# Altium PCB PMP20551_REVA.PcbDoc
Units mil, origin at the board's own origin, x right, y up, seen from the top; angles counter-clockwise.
Board outline 3500 x 1900 mil, 2 copper layers (Top Layer, Bottom Layer), stack 62 mil thick; 71 components, 27 nets, 155 pads, 31 vias.
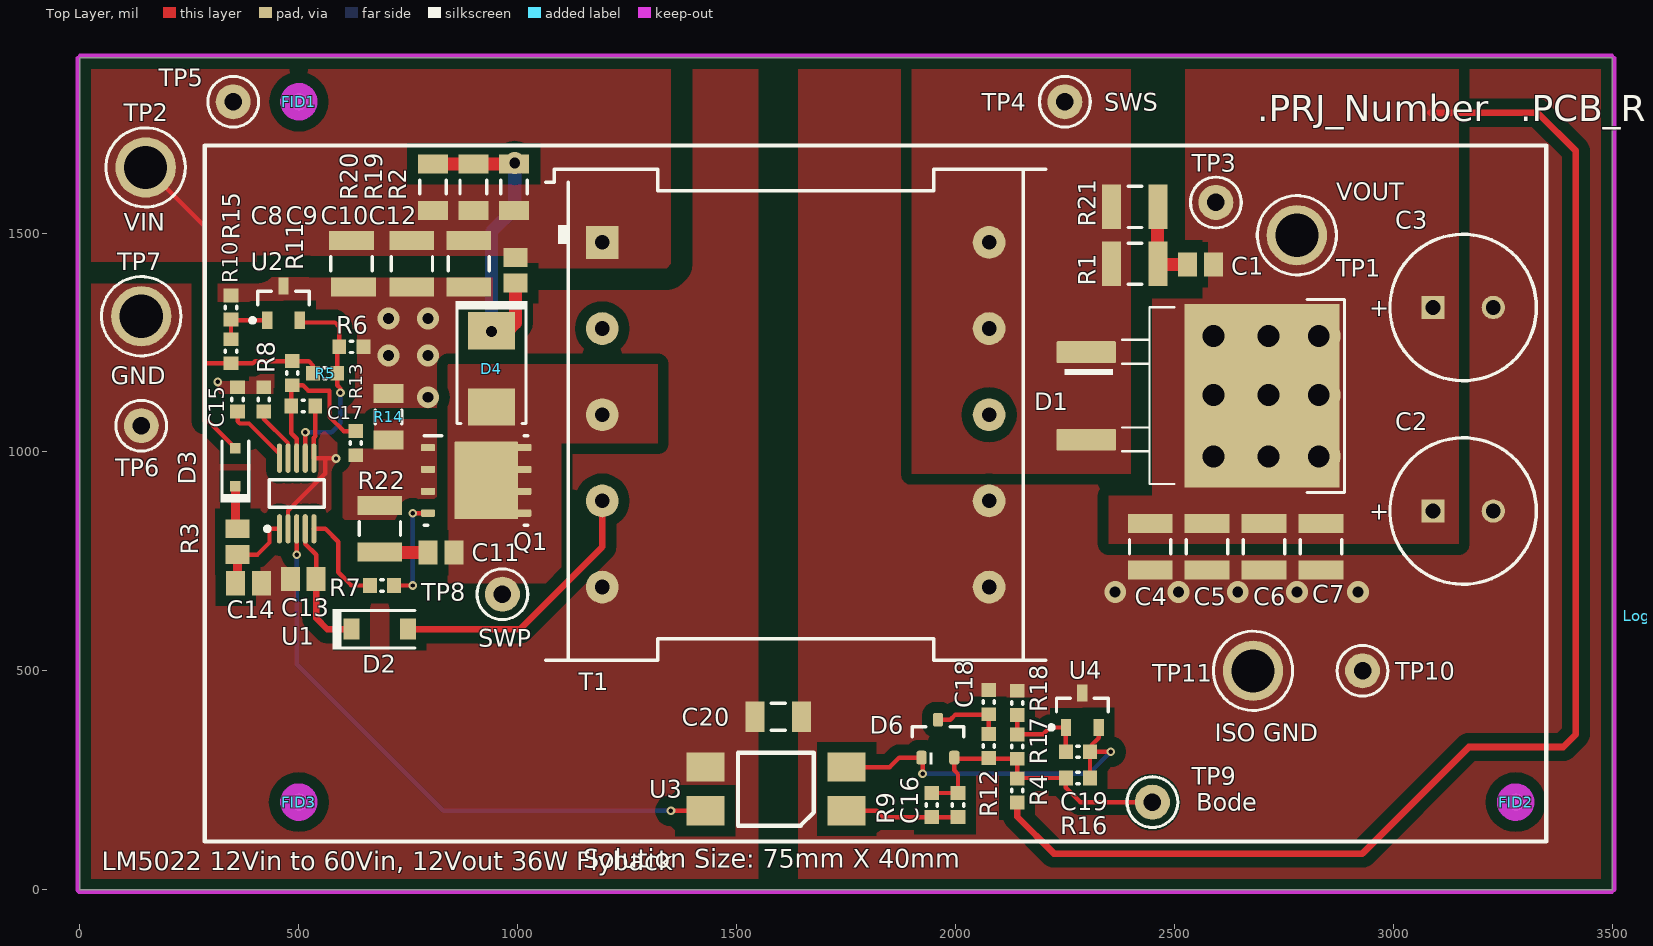
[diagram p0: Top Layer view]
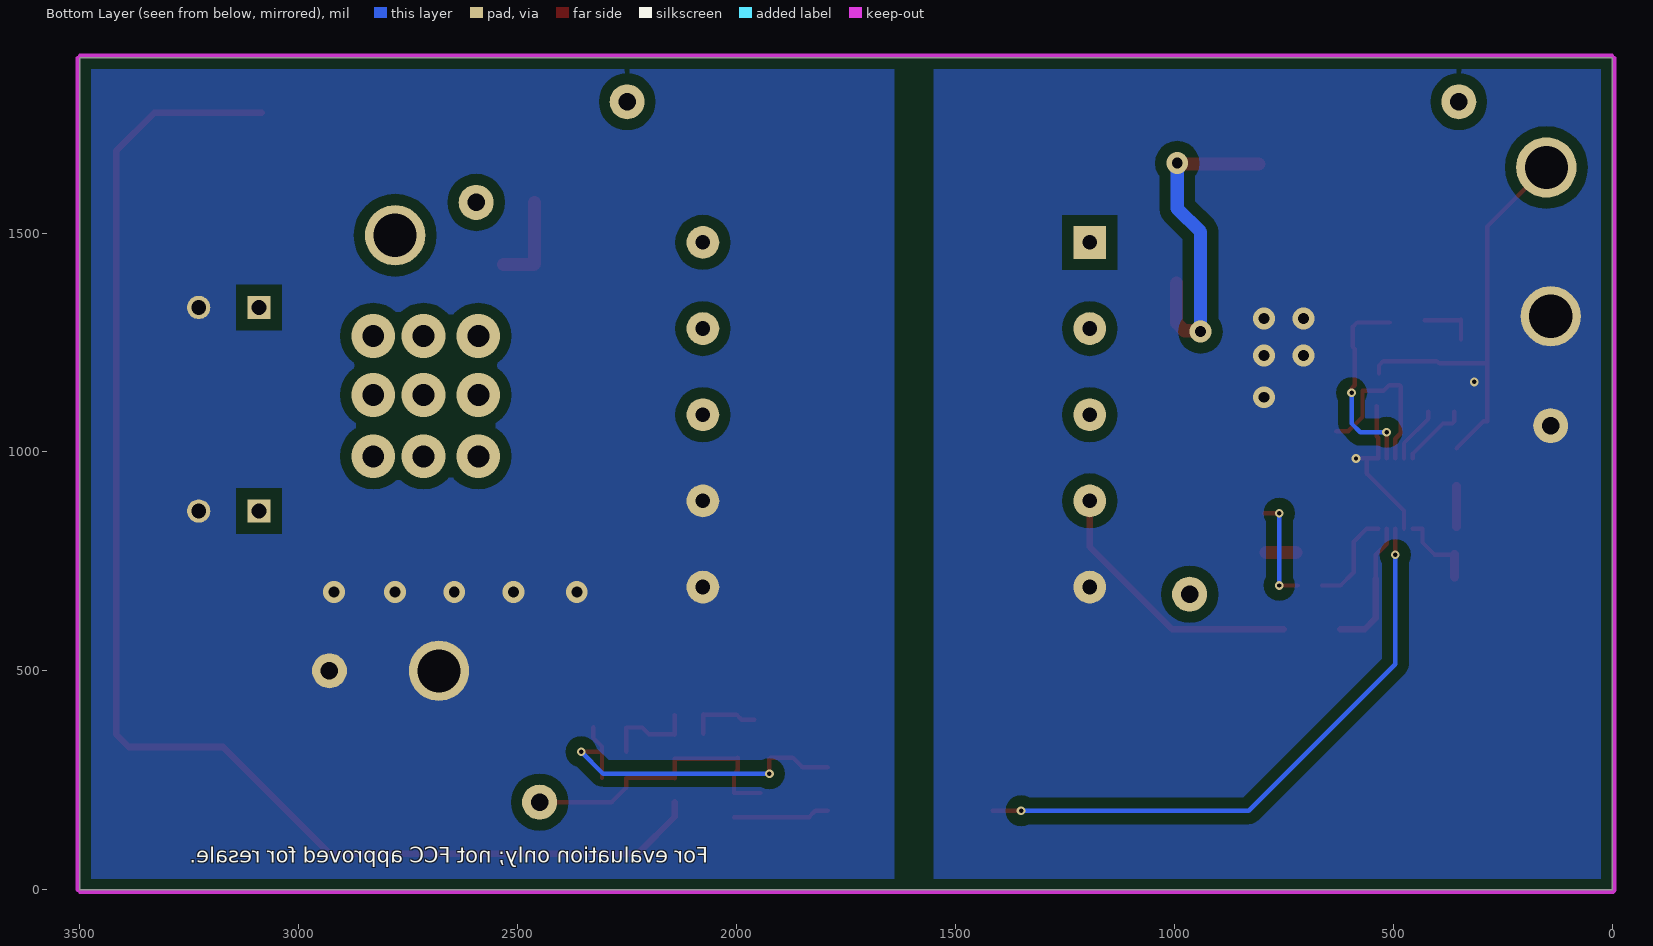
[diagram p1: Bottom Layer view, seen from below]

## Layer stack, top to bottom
Top Solder: solder mask 0.4, Solder Resist, Dk 3.5
Top Layer: signal copper 1.4
Dielectric1: core 59.2, FR-4, Dk 4.8
Bottom Layer: signal copper 1.4
Bottom Solder: solder mask 0.4, Solder Resist, Dk 3.5

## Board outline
0,0 3500,0 3500,1900 0,1900

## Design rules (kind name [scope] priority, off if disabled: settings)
AcuteAngle [All] p1: minimum=4.50000000000000E+0001 checktracksonly=FALSE
AssemblyTestPointUsage [All] p1: valid=2
Clearance Clearance_GND [(InPolygon AND InNet('GND')) vs InNet('ISO GND')] p1: gap=75
Clearance Clearance_Vin-GND [(InPolygon AND InNet('Vin')) vs InNet('GND')] p2: gap=50
Clearance Clearance_Keepouts [((IsTrack Or IsArc) And Not InPoly) And IsFree and IsKeepOut vs ((IsTrack Or IsArc) And Not InPoly) And IsFree and IsKeepOut] p3: gap=0
Clearance Clearance_BoardEdge_MountingHoles [OnCopper and InComponentClass('Mounting Holes') vs IsKeepOut] p4: gap=40
Clearance Clearance_BoardEdge_Poly [OnCopper and InPoly vs IsKeepOut] p5: gap=25
Clearance Clearance_BoardEdge [OnCopper and Not InComponentClass('Logo') and not InComponentClass('FiducialMark') and not InRegion(1000,500,4000,800) and Not IsKeepout vs IsKeepOut] p6: gap=50
Clearance Clearance_Poly [InPolygon] p7: gap=25
Clearance [All] p8: gap=7.87
ComponentClearance ComponentClearance_MountingHoles_FiducialMarks [InComponentClass('Mounting Holes') vs InComponentClass('FiducialMark')] p1: gap=50 collisioncheckmode=3 verticalgap=10 showdistances=FALSE
ComponentClearance ComponentClearance_Shunt [InComponentClass('Header') vs InComponentClass('Shunt')] p2: gap=0 collisioncheckmode=3 verticalgap=0 showdistances=FALSE
ComponentClearance ComponentClearance_Logo [InComponentClass('Logo')] p3: gap=50 collisioncheckmode=3 verticalgap=10 showdistances=FALSE
ComponentClearance ComponentClearance_ScrewToNut [(HasFootprint('NY PMS 440 0025 PH')) vs (HasFootprint('Keystone_1902C'))] p4: gap=5 collisioncheckmode=3 verticalgap=10 showdistances=FALSE
ComponentClearance ComponentClearance_MountingHoles [InComponentClass('Mounting Holes')] p5: gap=250 collisioncheckmode=3 verticalgap=100000 showdistances=FALSE
ComponentClearance ComponentClearance_SmallPassives [HasFootprint('0201*') or HasFootprint('0402*') or HasFootprint('0508') or HasFootprint('0603*') or HasFootprint('0612') or HasFootprint('0805*') or HasFootprint('0815*') or HasFootprint('0830*') or HasFootprint('1206*') or HasFootprint('1210*') or HasFootprint('1808*') or HasFootprint('1812*') or HasFootprint('1825*') or HasFootprint('2010*') or HasFootprint('2220*') or HasFootprint('2225*') or HasFootprint('2512*') or HasFootprint('2728*') or HasFootprint('3518*') vs HasFootprint('0201*') or HasFootprint('0402*') or HasFootprint('0508') or HasFootprint('0603*') or HasFootprint('0612') or HasFootprint('0805*') or HasFootprint('0815*') or HasFootprint('0830*') or HasFootprint('1206*') or HasFootprint('1210*') or HasFootprint('1808*') or HasFootprint('1812*') or HasFootprint('1825*') or HasFootprint('2010*') or HasFootprint('2220*') or HasFootprint('2225*') or HasFootprint('2512*') or HasFootprint('2728*') or HasFootprint('3518*')] p6: gap=20 collisioncheckmode=3 verticalgap=10 showdistances=FALSE
ComponentClearance ComponentClearance_THtoSMT [IsThruComponent vs IsSMTComponent] p7: gap=50 collisioncheckmode=3 verticalgap=30 showdistances=FALSE
ComponentClearance ComponentClearance_THtoTH [IsThruComponent vs IsThruComponent] p8: gap=80 collisioncheckmode=3 verticalgap=30 showdistances=FALSE
ComponentClearance [All] p9: gap=40 collisioncheckmode=3 verticalgap=10 showdistances=FALSE
DiffPairsRouting [All] p1: maxlimit=100 minlimit=10 mostfreqgap=10 toplayer_minwidth=15 toplayer_maxwidth=15 toplayer_prefwidth=15 bottomlayer_minwidth=15 bottomlayer_maxwidth=15 bottomlayer_prefwidth=15 maxuncoupledlength=1000
FabricationTestPointUsage TestPointUsage [All] p1: valid=2 allowmultiple=FALSE
FabricationTestpoint Testpoint [All] p1: side=3 testpointundercomponent=TRUE minsize=40 maxsize=100 preferedsize=60 minholesize=0 maxholesize=40 preferedholesize=32 testpointgrid=1 allowsidetop=TRUE allowsidebottom=TRUE usegrid=TRUE gridtolerance=0.01
FanoutControl Fanout_LCC [IsLCC] p1: bgadir=Out bgaviamode=Centered fanoutstyle=Auto fanoutdirection=Alternating viagrid=1 // Fanout_LCC (Default Rule)
FanoutControl Fanout_BGA [IsBGA] p2: bgadir=Out bgaviamode=Centered fanoutstyle=Auto fanoutdirection=Alternating viagrid=1 // Fanout_BGA (Default Rule)
FanoutControl Fanout_Default [All] p4: bgadir=Out bgaviamode=Centered fanoutstyle=Auto fanoutdirection=Alternating viagrid=1 // Fanout_Default (Default Rule)
FanoutControl Fanout_Small [(CompPinCount < 5)] p5: bgadir=Out bgaviamode=Centered fanoutstyle=Auto fanoutdirection=OutThenIn viagrid=1 // Fanout_Small (Default Rule)
HoleSize [All] p1: absolutevalues=TRUE maxlimit=251 minlimit=8 maxpercent=80.000 minpercent=20.000
MinimumAnnularRing MinimumAnnularRing_ThermalPadVias [IsVia and InAnyComponent] p1: minimumring=5.91
MinimumAnnularRing [All] p2: minimumring=9
MinimumSolderMaskSliver MinimumSolderMaskSliver_Logo [InComponentClass('Logo') vs InComponentClass('Logo')] p1: minsoldermaskwidth=0.7
MinimumSolderMaskSliver [All] p2: minsoldermaskwidth=3.94
PlaneConnect [All] p1: planeconnectstyle=Direct reliefexpansion=10 reliefentries=4 reliefconductorwidth=10 reliefairgap=10
PolygonConnect [All] p1: connectstyle=Direct reliefconductorwidth=10 reliefentries=4 polygonreliefangle="90 Angle" airgapwidth=10
RoutingVias ThermalPadVias [IsVia and InAnyComponent] p1: holewidth=7.87 width=19.68 viastyle="Through Hole" minholewidth=7.87 minwidth=19.68 maxholewidth=12.99 maxwidth=23.62
RoutingVias [All] p2: holewidth=16 width=34 viastyle="Through Hole" minholewidth=7.87 minwidth=26 maxholewidth=40 maxwidth=65
SilkToBoardRegionClearance [Not ((IsComment or IsDesignator) And (Hide <> 'False')) and not InRegion(1000,500,4000,800)] p1:
SilkToSilkClearance SilkToSilkClearance_Pb-FreeLogo [(HasFootprint('Pb-Free_Overlay_Medium') OR HasFootprint('Pb-Free_Overlay_Small')) vs (HasFootprint('Pb-Free_Overlay_Medium') OR HasFootprint('Pb-Free_Overlay_Small'))] p1: silktosilkclearance=0
SilkToSilkClearance [All] p2: silktosilkclearance=4
SilkToSolderMaskClearance SilkToComonentPadClearance [IsPad and InAnycomponent] p1: minsilkscreentomaskgap=5 clearancetoexposedcopper=TRUE
SilkToSolderMaskClearance "Silk to Solder Mask Opening" [All] p2: minsilkscreentomaskgap=4 clearancetoexposedcopper=FALSE
SolderMaskExpansion [All] p1: expansion=1.97
Width [All] p1: maxlimit=100 minlimit=6 preferedwidth=10 checkconnectedcopper=TRUE
15 further rules are at their usual default settings.

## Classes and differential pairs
component class PMP20551_REVA_Hardware: FID1 FID2 FID3 Logo1 ZZ1 ZZ2 ZZ3
component class FiducialMark: FID1 FID2 FID3
component class AssemblyNote: ZZ1 ZZ2 ZZ3
component class PMP20551_REVA: C1 C2 C3 C4 C5 C6 C7 C8 C9 C10 C11 C12 C13 C14 C15 C16 C17 C18 C19 C20 D1 D2 D3 D4 D6 Q1 R1 R2 R3 R4 R5 R6 R7 R8 R9 R10 R11 R12 R13 R14 R15 R16 R17 R18 R19 R20 R21 R22 T1 TP1 TP2 TP3 TP4 TP5 TP6 TP7 TP8 TP9 TP10 TP11 U1 U2 U3 U4

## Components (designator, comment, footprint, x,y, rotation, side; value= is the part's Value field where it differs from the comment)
C1 "GRM2165C2A471JA01D" 0805L 2559.92,1428.19 r180 top
C2 "UHV1C471MPD" HV_800x1150 3160,865 r0 top
C3 "UHV1C471MPD" HV_800x1150 3160,1330 r0 top
C4 "GRM32ER71E226KE15L" 1210L#1 2444.92,783.19 r270 top
C5 "GRM32ER71E226KE15L" 1210L#1 2574.92,783.19 r270 top
C6 "GRM32ER71E226KE15L" 1210L#1 2704.92,783.19 r270 top
C7 "GRM32ER71E226KE15L" 1210L#1 2834.92,783.19 r270 top
C8 "GRM32ER71K475KE14L" 1210L#2 625,1430 r270 top
C9 "GRM32ER71K475KE14L" 1210L#1 758.15,1430 r270 top
C10 "GRM32ER71K475KE14L" 1210L#1 888.15,1430 r270 top
C11 "GRM2195C2A152JA01D" 0805L 825,770 r180 top
C12 "GRM21BR72A104KAC4L" 0805L 995,1415 r270 top
C13 "GRM21BR71E225KA73L" 0805L 510,710 r180 top
C14 "GRM21AR72A224KAC5L" 0805L 385,700 r0 top
C15 "GRM188R70J473KA01D" 0603L 360,1120 r90 top
C16 "DNP" 0603L 2006.01,193.29 r270 top
C17 "GRM1885C1H101JA01D" 0603L 510,1105 r0 top
C18 "GRM188R71E105KA12D" 0603L 2076.01,428.29 r90 top
C19 "GRM188R71E224KA88D" 0603L 2280,315 r180 top
C20 "GRM31BR73A102KW01L" 1206L 1595,395 r180 top
D1 "MBRB20100CTT4G" DDPAK 2544.92,1128.19 r0 top
D2 "" SOD-123 685,595 r0 top
D3 "BAT54HT1G" SOD-323 355,965 r90 top
D4 "MBRS1100T3G" SMB 940,1190 r270 top
D6 "BAT54S-7-F" SOT-23L 1960,345 r90 top
FID1 "Fiducial" Fiducial10-20 500,1800 r0 top
FID2 "Fiducial" Fiducial10-20 3280,200 r0 top
FID3 "Fiducial" Fiducial10-20 500,200 r0 top
Logo1 "FCC disclaimer" FCC_disclaimer 3578,626 r90 top
Q1 "CSD19534Q5A" DQJ0008A 905,935 r0 top
R1 "CRCW12103R30FKEAHP" 1210L#1 2410,1430 r0 top
R2 "CRCW120639K0JNEA" 1206L 991.61,1605 r270 top
R3 "CRCW08053R30JNEA" 0805L 360,795 r90 top
R4 "CRCW060347R0JNEA" 0603L 2141.01,226.64 r270 top
R5 "CRCW060369K8FKEA" 0603L 560,1180 r180 top
R6 "CRCW060310K0FKEA" 0603L 620,1240 r180 top
R7 "CRCW06030000Z0EA" 0603L 690,695 r180 top
R8 "CRCW060368K1FKEA" 0603L 420,1120 r270 top
R9 "CRCW06034K99FKEA" 0603L 1946.01,193.29 r90 top
R10 "CRCW0603523KFKEA" 0603L 345,1230 r90 top
R11 "CRCW06031M50FKEA" 0603L 485,1180 r90 top
R12 "CRCW060347K0FKEA" 0603L 2076.01,328.29 r270 top
R13 "CRCW06036K81FKEA" 0603L 630,1020 r270 top
R14 "WSLP1206R0200FEA" 1206L 705,1080 r270 top
R15 "CRCW060310K2FKEA" 0603L 345,1330 r90 top
R16 "CRCW0603499RFKEA" 0603L 2280,255 r0 top
R17 "CRCW060310K7FKEA" 0603L 2141.01,326.64 r270 top
R18 "CRCW06031K24FKEA" 0603L 2141.01,426.64 r90 top
R19 "CRCW120639K0JNEA" 1206L 898.61,1605 r270 top
R20 "CRCW120639K0JNEA" 1206L 806.61,1605 r270 top
R21 "CRCW12103R30FKEAHP" 1210L#1 2410,1560 r0 top
R22 "CRCW12103R30FKEAHP" 1210L#1 685,825 r270 top
T1 "86H-15177" MPS 1635,1085 r0 top
TP1 "VOUT" Keystone1502-2 2780,1495 r0 top
TP2 "VIN" Keystone1502-2 150,1650 r0 top
TP3 "5000" Keystone5000 2595,1570 r0 top
TP4 "SWS" Keystone5002 2250,1800 r0 top
TP5 "5000" Keystone5000 350,1800 r0 top
TP6 "5001" Keystone5001 140,1060 r0 top
TP7 "GND" Keystone1502-2 140,1310 r0 top
TP8 "SWP" Keystone5002 965,675 r0 top
TP9 "Bode" Keystone5002 2450,200 r0 top
TP10 "5001" Keystone5001 2930,500 r0 top
TP11 "ISO GND" Keystone1502-2 2680,500 r0 top
U1 "LM5022MME/NOPB" MUB10A_N 495,905 r90 top
U2 "LMV431BIMFX/NOPB" MF03A_L 465,1340 r90 top
U3 "PS2501L-1-E3-L-A" PS2501L 1590,230.01 r180 top
U4 "LMV431BIMFX/NOPB" MF03A_L 2290,410 r90 top
ZZ1 "These assemblies are ESD sensitive, ESD precautions shall be observed." AssemblyNote 185,3829.11 r0 top
ZZ2 "These assemblies must be clean and free from flux and all contaminants. Use of no clean flux is not acceptable." AssemblyNote 185,3740.56 r0 top
ZZ3 "These assemblies must comply with workmanship standards IPC-A-610 Class 2, unless otherwise specified." AssemblyNote 185,3652 r0 top

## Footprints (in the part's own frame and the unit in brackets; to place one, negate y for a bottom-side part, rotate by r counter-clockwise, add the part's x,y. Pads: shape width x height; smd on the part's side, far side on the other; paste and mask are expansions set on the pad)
0603L [mm] "0603 from SM-752 data"
  rect 0.8x0.85 smd: 1(-0.7,0) 2(0.7,0)
  silkscreen extent -0.07,-0.33 0.07,0.33, body extent -0.87,-0.47 0.87,0.47, height 1
0805L [mm] "0805 from SM-752 data"
  rect 1.1x1.4 smd: 1(-0.75,0) 2(0.75,0)
  body extent -1.1,-0.72 1.1,0.72, height 1.45
1206L [mm] "1206 from SM-752 data"
  rect 1.1x1.75 smd: 1(-1.35,0) 2(1.35,0)
  silkscreen extent -0.4,-0.77 0.4,0.77, body extent -1.7,-0.9 1.7,0.9, height 1.35
1210L#1 [mm] "1210 from SM-752 data"
  rect 1.1x2.6 smd: 1(-1.35,0) 2(1.35,0)
  silkscreen extent -0.4,-1.2 0.4,1.2, body extent -1.7,-1.35 1.7,1.35, height 1.35
1210L#2 [mm] "1210 from SM-752 data"
  rect 1.1x2.6 smd: 1(-1.35,-0.119) 2(1.35,0)
  silkscreen extent -0.4,-1.32 0.4,1.08, body extent -1.7,-1.47 1.7,1.35, height 1.35
AssemblyNote [mil] "Assembly Note"
DDPAK [mil] "D2-PAK, 3-Pads, Body 9.7x10.4mm (max), TO-263AB, using Vishay Silionix recommended pad sizes"
  rrect8% 135x49.49 smd: 1(-246.06,100) 3(-246.06,-100)
  rrect1% 355x420 smd paste-181.1: 4(155.51,0)
  silkscreen extent -295,-220 344,220, body extent -295,-202 324,202, height 180
DQJ0008A [mm] "SMD, 8-Leads, Body 5.75x4.9mm"
  rrect24% 0.81x0.41 smd: 1(-2.795,1.905) 2(-2.795,0.635) 3(-2.795,-0.635) 4(-2.795,-1.905) 5(2.795,-1.905) 6(2.795,-0.635) 7(2.795,0.635) 8(2.795,1.905)
  rrect8% 1.58x1.25 on Top Paste: 9(-0.38,-1.45) 9(-0.38,0) 9(-0.38,1.45) 9(1.4,-1.45) 9(1.4,0) 9(1.4,1.45)
  rrect3% 3.7x4.5 smd paste-2.5: 9(0.59,0)
  silkscreen extent -3,-2.6 3,2.6, body extent -3.13,-2.45 3.13,2.45, height 1.15
FCC_disclaimer [mil]
Fiducial10-20 [mm]
  round 1 smd mask+0.5: 1(0,0)
  Top Layer keep-out circle w1.178: c0,0 r0.5
HV_800x1150 [mm] "TH, 2-Leads, Dia 8mm, Pin Spacing 3.5mm"
  rect 1.35x1.35 hole 0.85: 1(-1.75,0)
  round 1.35 hole 0.85: 2(1.75,0)
  silkscreen extent -4.25,-4.25 4.25,4.25, body extent -4.22,-4.24 4.24,4.24, height 12.51
Keystone1502-2 [mm] "Double Turret"
  round 3.5 hole 2.5: 1(0,0)
  silkscreen extent -2.3,-2.3 2.3,2.3, body extent -1.6,-1.6 1.59,1.6, height 5.62
Keystone5000 [mil] "For Keystone 500x miniature loop terminals"
  round 80 hole 40: 1(0,0)
  silkscreen extent -58,-58 58,58, body extent -49,-49 49,49, height 182
Keystone5001 [mil] "For Keystone 500x miniature loop terminals"
  round 80 hole 40: 1(0,0)
  silkscreen extent -58,-58 58,58, body extent -49,-49 49,49, height 182
Keystone5002 [mil] "For Keystone 500x miniature loop terminals"
  round 80 hole 40: 1(0,0)
  silkscreen extent -58,-58 58,58, body extent -49,-49 49,49, height 182
MF03A_L [mm] "SOT23, 3-Leads, Body 2.9x1.3mm, Pitch 0.95mm, Lead Span 2.4mm, IPC High Density"
  rect 1x0.6 smd: 1(-1,0.95) 2(-1,-0.95) 3(1,0)
  silkscreen extent -1.12,-1.5 0.7,1.92, body extent -0.7,-1.5 0.7,1.5, height 1.12
MPS [mm] "TH, 10-Leads, Body 29x28.5mm, Pitch 5.08mm"
  rect 1.9x1.9 hole 0.85: 1(-11.225,10)
  round 1.9 hole 0.85: 2(-11.225,5) 3(-11.225,0) 4(-11.225,-5) 5(-11.225,-10) 6(11.225,-10) 7(11.225,-5) 8(11.225,0) 10(11.225,10)
  round 1.9 hole 0.852: 9(11.225,5)
  silkscreen extent -14.5,-14.25 14.5,14.25, body extent -14.5,-14.25 14.5,14.25, height 25
MUB10A_N [mm] "TSSOP, 10-Leads, Body 3x3mm, Pitch 0.5mm, IPC Medium Density"
  oval 1.7x0.3 smd: 1(-2.05,1) 2(-2.05,0.5) 3(-2.05,0) 4(-2.05,-0.5) 5(-2.05,-1) 6(2.05,-1) 7(2.05,-0.5) 8(2.05,0) 9(2.05,0.5) 10(2.05,1)
  silkscreen extent -2.17,-1.6 0.8,1.82, body extent -1.6,-1.6 1.6,1.6, height 1.09
PS2501L [mm] "NEC optocoupler"
  rect 2.2x1.7 smd: 1(-4.1,1.27) 2(-4.1,-1.27) 3(4.1,-1.27) 4(4.1,1.27)
  silkscreen extent -2.2,-2.1 2.2,2.12, body extent -5,-2.29 5,2.29, height 3.87
SMB [mil] "Molded Diode, 2-Leads, Body 5.4x3.6mm, IPC Medium Density, based on OnSemi component dimensions"
  rect 85x107.99 smd: 1(-87.01,0) 2(87.01,0)
  silkscreen extent -155,-82 125,82, body extent -106,-71 106,71, height 91
SOD-123 [mm] "On Semi recommended land pattern"
  rect 0.915x1.22 smd: 1(-1.637,0) 2(1.637,0)
  silkscreen extent -2.74,-1.17 2.03,1.17, body extent -1.93,-0.9 1.93,0.9, height 1.35
SOD-323 [mm] "NXP recommended land pattern"
  rect 0.6x0.6 smd paste-0.05: 1(-1.1,0) 2(1.1,0)
  silkscreen extent -2.06,-0.86 1.53,0.86, body extent -1.3,-0.67 1.3,0.68, height 1.1
SOT-23L [mm] "SOT23, 3-Leads, Body 2.9x1.3mm, Pitch 0.95mm, Lead Span 2.5mm, IPC High Density"
  rrect50% 0.8x0.6 smd: 1(-1.1,0.95) 2(-1.1,-0.95) 3(1.1,0)
  silkscreen extent -1.5,-1.5 0.7,1.5, body extent -1.16,-1.45 1.21,1.45, height 1

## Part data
C1: "CAP, CERM, 470 pF, 100 V, +/- 5%, C0G/NP0, 0805"
C2 C3: library part UHV1c471mpd, "CAP, AL, 470 µF, 16 V, +/- 20%, TH"
C4 C5 C6 C7: "CAP, CERM, 22 µF, 25 V, +/- 10%, X7R, 1210"
C8 C9 C10: "CAP, CERM, 4.7 µF, 80 V, +/- 10%, X7R, 1210"
C11: "CAP, CERM, 1500 pF, 100 V, +/- 5%, C0G/NP0, 0805"
C12: "CAP, CERM, 0.1 µF, 100 V, +/- 10%, X7R, 0805"
C13: "CAP, CERM, 2.2 µF, 25 V, +/- 10%, X7R, 0805"
C14: "CAP, CERM, 0.22 µF, 100 V, +/- 10%, X7R, 0805"
C15: "CAP, CERM, 0.047 µF, 6.3 V, +/- 10%, X7R, 0603"
C16: library part GRM188R71E224KA88D, "CAP, CERM, 0.22 µF, 25 V, +/- 10%, X7R, 0603"
C17: "CAP, CERM, 100 pF, 50 V, +/- 5%, C0G/NP0, 0603"
C18: "CAP, CERM, 1 µF, 25 V, +/- 10%, X7R, 0603"
C19: "CAP, CERM, 0.22 µF, 25 V, +/- 10%, X7R, 0603"
C20: "CAP, CERM, 1000 pF, 1000 V, +/- 10%, X7R, 1206"
D1: "Diode, Schottky, 100 V, 20 A, DDPAK"
D2: library part 1N4148W-7-F, "Diode, Ultrafast, 100V, 0.15A, SOD-123"
D3: "Diode, Schottky, 30 V, 0.2 A, SOD-323"
D4: "Diode, Schottky, 100 V, 1 A, SMB"
D6: "Diode, Schottky, 30 V, 0.2 A, SOT-23"
FID1 FID2 FID3: "Fiducial mark.  There is nothing to buy or mount."
Logo1: library part FCC_disclaimer, "FCC_disclaimer"
Q1: "MOSFET, N-CH, 100 V, 10 A, DQJ0008A (VSONP-8)"
R1 R21 R22: "RES, 3.30, 1%, 0.75 W, AEC-Q200 Grade 0, 1210"
R2 R19 R20: "RES, 39 k, 5%, 0.25 W, 1206"
R3: "RES, 3.3, 5%, 0.125 W, 0805"
R4: "RES, 47, 5%, 0.1 W, 0603"
R5: "RES, 69.8 k, 1%, 0.1 W, 0603"
R6: "RES, 10.0k ohm, 1%, 0.1W, 0603"
R7: "RES, 0, 5%, 0.1 W, 0603"
R8: "RES, 68.1 k, 1%, 0.1 W, 0603"
R9: library part CRCW06034k99FKEA, "RES, 4.99 k, 1%, 0.1 W, 0603"
R10: "RES, 523 k, 1%, 0.1 W, 0603"
R11: "RES, 1.50 M, 1%, 0.1 W, 0603"
R12: "RES, 47.0 k, 1%, 0.1 W, AEC-Q200 Grade 0, 0603"
R13: "RES, 6.81 k, 1%, 0.1 W, 0603"
R14: "RES, 0.02, 1%, 1 W, 1206"
R15: "RES, 10.2 k, 1%, 0.1 W, 0603"
R16: library part CRCW0603499rFKEA, "RES, 499, 1%, 0.1 W, 0603"
R17: "RES, 10.7 k, 1%, 0.1 W, 0603"
R18: "RES, 1.24 k, 1%, 0.1 W, 0603"
T1: library part MPS, "Transformer, 18 uH, TH"
TP1 TP2 TP7 TP11: library part 1502-2, "Terminal, Turret, TH, Double"
TP3 TP5: "Test Point, TH, Miniature, Red"
TP4 TP8 TP9: library part 5002, "Test Point, TH, Miniature, White"
TP6 TP10: "Test Point, TH, Miniature, Black"
U1: "60V Low Side Controller for Boost and SEPIC, 10-pin MSOP, Pb-Free"
U2 U4: "Low-Voltage (1.24V) Adjustable Precision Shunt Regulators, 3-pin SOT-23, Pb-Free"
U3: "Optocoupler, 5 kV, 200-400% CTR, SMT"
ZZ1 ZZ2 ZZ3: library part AssemblyNote

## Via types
v1: diameter 50, hole 25, Top Layer to Bottom Layer, 12 vias
v2: diameter 20, hole 10, Top Layer to Bottom Layer, 10 vias
v3: diameter 100, hole 50, Top Layer to Bottom Layer, 9 vias

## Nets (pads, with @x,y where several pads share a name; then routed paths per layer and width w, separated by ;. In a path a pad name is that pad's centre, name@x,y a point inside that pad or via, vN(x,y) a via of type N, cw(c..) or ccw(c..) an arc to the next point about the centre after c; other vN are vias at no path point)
AUX: D2.2 T1.4 | length 626.6
  Top Layer w15: D2.2 1005,595 1193.07,783.07 T1.4
COMP: U1.3 U3.4 | length 1366.6
  Top Layer w10: v2(495,765) U1.3 ; v2@1351.42,180 U3.4@1415,180
  Bottom Layer w10: v2(495,765) 495,515 830,180 v2(1350,180)
CS: C17.1 R11.1 R13.1 U1.8 | length 396.6
  Top Layer w10: U1.8 495,1030 482.44,1042.56 C17.1 482.44,1149.88 R11.1 509.31,1152.44 521.75,1140 570,1140 570,1080 602.44,1047.56 R13.1
GND: C8.2 C9.2 C10.2 C13.2 C14.2 C15.2 C17.2 C20.2 R6.1 R8.1 R14.1 R15.2 T1.5 TP6.1 TP7.1 U1.2 U1.6 U2.3 U3.3 | length 368.5
  Top Layer w10: U1.2 475.31,865.63 560,950.32 560,985.71 ; C17.2 537.87,1105 537.87,1035.53 534.37,1032.02 U1.6 560,985.71 ; v2(585,985) 584.29,985.71 560,985.71
  other v1: 795,1125 705,1220 795,1220 705,1305 795,1305
  other v2: 315,1160
"ISO GND": C2.2 C3.2 C4.2 C5.2 C6.2 C7.2 C18.2 C20.1 R18.2 T1.6 T1.7 TP10.1 TP11.1 U4.3
  other v1: 2365,680 2510,680 2645,680 2780,680 2920,680
NetC1_2: C1.2 R1.2 R21.2 | length 208.9
  Top Layer w30: R1.2@2461.61,1430 R21.2@2461.61,1570 ; R1.2@2463.43,1428.19 C1.2 C1.2@2532.36,1428.19
NetC11_2: C11.2 R22.2 | length 68.9
  Top Layer w30: R22.2@721.69,770 C11.2@790.55,770
NetC12_2: C12.2 D4.1 R2.1 R19.1 R20.1 | length 745
  Top Layer w30: R20.1 R19.1 R2.1 ; D4.1 977.01,1277.01 995,1295 C12.2
  Bottom Layer w30: v1(940,1275) 940,1502.76 993.23,1555.98 v1(993.23,1660)
NetC16_1: C16.1 D6.2 R4.1 R9.2 R12.2 R16.1 R17.2 TP9.1 | length 675.5
  Top Layer w10: R9.2 C16.1 2006.01,263.99 1997.4,272.6 D6.2 ; D6.2@2000.01,299.08 R17.2 R4.1 2141.81,255 R16.1 2252.44,232.56 2285,200 TP9.1
NetC16_2: C16.2 R9.1 U3.1 | length 220.5
  Top Layer w10: U3.1@1791.42,180.01 1819.99,180.01 1834.27,165.73 C16.2
NetC18_1: C18.1 D6.3 R12.1 | length 166
  Top Layer w10: D6.3 1988.31,388.31 2000,400 2075.27,400 C18.1 R12.1
NetC19_1: C19.1 D6.1 R16.2 U3.2 U4.2 | length 796.5
  Top Layer w10: U3.2@1791.42,280.01 1850.01,280.01 1871.69,301.69 D6.1 ; v2(1925,265) D6.1@1925,299.29 ; R16.2 C19.1 ; U4.2 2327.4,346.65 2307.56,326.81 C19.1 ; v2(2355,315) C19.1
  Bottom Layer w10: v2(1925,265) 2305,265 v2(2355,315)
NetC19_2: C19.2 R17.1 R18.1 U4.1 | length 218.5
  Top Layer w10: R18.1 R17.1 2141.81,355 2200,355 2215.47,370.47 2252.44,370.47 C19.2
NetD3_1: D3.1 R3.2 | length 92.2
  Top Layer w20: R3.2@355,829.53 D3.1
NetQ1_1: Q1.1 Q1.2 Q1.3 R13.2 R14.2 R22.1
NetQ1_4: Q1.4 R7.1 | length 242.4
  Top Layer w10: R7.1 v2(760,695) ; v2(760,860) Q1.4
  Bottom Layer w10: v2(760,695) v2(760,860)
NetR10_2: R10.2 R15.1 U2.1 | length 125.7
  Top Layer w10: R10.2 R15.1 ; R15.1@346.81,1300.63 U2.1
OUT: R7.2 U1.5 | length 222.6
  Top Layer w10: U1.5 560.71,824.29 590,795 590,725 620,695 R7.2
RT: R8.2 U1.9 | length 129.6
  Top Layer w10: R8.2 420,1075.46 475.31,1020.14 U1.9
SS: C15.1 U1.10 | length 158.8
  Top Layer w10: C15.1 360,1070 365,1065 386.18,1065 455.63,995.55 U1.10
SWP: C11.1 D4.2 Q1.5 Q1.6 Q1.7 Q1.8 Q1.9@928.23,935 T1.3 TP8.1
SWS: D1.1 D1.3 R1.1 R21.1 T1.9 T1.10 TP4.1
UVLO: R5.1 R6.2 U1.7 U2.2 | length 462.5
  Top Layer w10: U2.2@507.44,1295.59 582.44,1295.59 592.44,1285.59 R6.2 587.56,1235.12 R5.1 587.56,1152.44 595,1145 v2(595,1135) ; U1.7 514.68,1044.68 v2(515,1045)
  Bottom Layer w10: v2(515,1045) 575,1045 595,1065 v2(595,1135)
VCC: C13.1 D2.1 U1.4 | length 305.7
  Top Layer w10: U1.4 514.68,789.86 539.53,765.02 C13.1
  Top Layer w15: C13.1 539.53,620.47 565,595 D2.1
VIN: C8.1 C9.1 C10.1 C12.1 D3.2 R2.2 R5.2 R10.1 R11.2 R19.2 R20.2 T1.1 TP2.1 TP5.1 | length 1000.2
  Top Layer w10: TP2.1 285,1515 285,1070 293.31,1070 D3.2 ; 287.56,1202.44 R10.1 394.88,1202.44 400,1207.56 R11.2 522.44,1207.56 532.44,1197.56 R5.2
"VIN U1": C14.1 R3.1 U1.1 | length 195.7
  Top Layer w10: C14.1@355.47,710 C14.1@360,714.53 ; R3.1 405.47,765.47 432.99,792.99 432.99,824.29 U1.1
  Top Layer w20: C14.1@360,714.53 R3.1
VOUT: C1.1 C2.1 C3.1 C4.1 C5.1 C6.1 C7.1 D1.4 R4.2 TP1.1 TP3.1 | length 3158
  Top Layer w15: R4.2 2141.01,166.49 2225,82.5 2929.72,82.5 3173.2,325.98 3388.48,325.98 3417.5,355 3417.5,1687.5 3330,1775 3085,1775
  other v3: 2590,990 2715,990 2830,990 2590,1130 2715,1130 2830,1130 2590,1265 2715,1265 2830,1265
pads on no net: FID1.1 FID2.1 FID3.1 Q1.9@890.04,877.91 Q1.9@890.04,935 Q1.9@890.04,992.09 Q1.9@960.12,877.91 Q1.9@960.12,935 Q1.9@960.12,992.09 T1.2 T1.8

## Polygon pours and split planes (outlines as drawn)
VOUT on Top Layer "Vout" (solid, remove dead copper, pour order 16): 2525,1900 2525,1485 2565,1485 2565,1350 2450,1350 2450,900 2350,900 2350,790 3150,790 3150,1900
SWS on Top Layer "SWS" (solid, remove dead copper, pour order 15): 1900,1900 1900,950 2400,950 2400,1900
NetQ1_1 on Top Layer "NetQ1_1" (solid, remove dead copper, pour order 14): 830,1050 830,880 742.09,880 737.09,875 737.09,845 605,845 600,850 600,1020 640.67,1020 650.67,1030 660,1039.33 660,1045 660,1075 830,1075
SWP on Top Layer "SWP" (solid, remove dead copper, pour order 13): 840,1200 840,700 1100,700 1100,1020 1320,1020 1320,1200
VIN on Top Layer "Vin" (solid, remove dead copper, pour order 12): 0,1900 0,1435 940,1435 955,1420 1085,1420 1340,1420 1350,1430 1350,1900 0,1900
"ISO GND" on Top Layer "ISO GND" (solid, remove dead copper, pour order 18): 1640.36,1900 1640.36,0 3500,0 3500,1895 3505,1900
GND on Top Layer "GND" (solid, remove dead copper, pour order 17): 0,1900 0,5 -5,0 1550,0 1550,1900
"ISO GND" on Bottom Layer "ISO GND" (solid, remove dead copper, pour order 20): 1640,1900 1640,0 3500,0 3500,1900
GND on Bottom Layer "GND" (solid, remove dead copper, pour order 19): 0,1899.52 0,4.52 -5,-0.48 1550,-0.48 1550,1899.52

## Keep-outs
Keep-Out Layer:
  lines w10: -5,1900 -5,0 ; 0,1905 3500,1905 ; 3500,-5 0,-5 ; 3505,0 3505,1900 ; -5,0 ccw(c0,0) 0,-5 ; -5,0 ccw(c0,0) 0,-5
  text ".Layer_Name" at 577,-858.49 h60

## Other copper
Top Layer:
  text ".Layer_Name" at 577,-858.49 h60
Bottom Layer:
  text ".Layer_Name" at 577,-858.49 h60

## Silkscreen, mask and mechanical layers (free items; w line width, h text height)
Top Overlay:
  lines w10: 285,110 3350,110 3350,1700 285,1700 285,110
  text ".PRJ_Number" at 2690,1755 h60
  text ".PCB_Rev" at 3290,1755 h60
  text "Solution Size: 75mm X 40mm" at 1150,35 h72.83
  text "LM5022 12Vin to 60Vin, 12Vout 36W Flyback" at 50,30 h72.83
  text ".Layer_Name" at 577,-858.49 h60
Bottom Overlay:
  text ".Layer_Name" at 577,-858.49 h60
Top Paste:
  text ".Layer_Name" at 577,-858.49 h60
Bottom Paste:
  text ".Layer_Name" at 577,-858.49 h60
Top Solder:
  text ".Layer_Name" at 577,-858.49 h60
  text ".Layer_Name" at 577,-858.49 h60
Bottom Solder:
  text ".Layer_Name" at 577,-858.49 h60
Drill Guide:
  text ".Layer_Name" at 577,-858.49 h60
M1 Board Outline:
  the board outline again, w10
  text ".Layer_Name" at 577,-858.49 h60
M2 Board Dimensions:
  rectangle: 0,-275 125,-150
  rectangle: 125,-400 500,-275
  lines w7: 0,-275 1000,-275 ; 125,-400 125,-150 ; 250,-400 250,-150 ; 500,-400 500,-150 ; 750,-400 750,-150 ; 0,-400 1000,-400 1000,-150 0,-150 0,-400
  text ".Layer_Name" at 577,-858.49 h60
M3 3D STEP Top:
  text ".Layer_Name" at 577,-858.49 h60
M4 3D STEP Bottom:
  text ".Layer_Name" at 577,-858.49 h60
M5 Assembly Top:
  lines w10: -292,-930.17 6308,-930.17 ; -292,-726.83 6310,-726.83 ; -292,-523.5 -292,-1133.5 3713,-1133.5 6310,-1133.5 6310,-523.5 -291.5,-523.5 -291.5,-1133.5 1284,-1133.5 ; 2173,-1133.5 2173,-523.5 ; 3440,-726.83 3440,-523.5 ; 4280,-726.83 4280,-523.5 ; 4902,-1140 4902,-937.17
  text "COMPONENTS MARKED 'DNP' SHOULD NOT BE POPULATED." at 1153.5,-318.5 h60
  text "ASSEMBLY VARIANT:" at 1153,-434 h60
  text ".VariantName" at 2189,-434 h60
  text "PCB VIEWED FROM TOP SIDE" at -228.5,-655.67 h60
  text "BOARD #:" at 2248,-655.67 h60
  text ".PRJ_Number" at 2793.5,-655.67 h60
  text "REV:" at 3638,-655.67 h60
  text ".PCB_Rev" at 3929.5,-655.67 h60
  text "SVN REV:" at 4476,-655.67 h60
  text ".VersionControl_RevNumber" at 4982,-655.67 h60
  text "TID #:" at 2248,-859 h60
  text ".TID" at 2793.5,-859 h60
  text "PLOT NAME =" at -228.5,-1064.34 h60
  text ".plot_File_Name" at 577,-1064.34 h60
  text "GENERATED    :" at 2250,-1064.34 h60
  text ".Print_Date" at 3119.5,-1064.34 h60
  text ".Print_Time" at 3848.5,-1064.34 h60
  text "TEXAS INSTRUMENTS" at 5113,-1064.34 h60
M6 Assembly Bottom:
  lines w10: -292.5,-727.33 6309.5,-727.33 ; -290.5,-930.67 6309.5,-930.67 ; 1115.5,-1140.5 1115.5,-937.67 ; 1737.5,-727.33 1737.5,-524 ; 2577.5,-727.33 2577.5,-524 ; 3844.5,-1134 3844.5,-524 ; 4733.5,-1134 6309,-1134 6309,-524 -292.5,-524 -292.5,-1134 2304.5,-1134 6309.5,-1134 6309.5,-524
  text "COMPONENTS MARKED 'DNP' SHOULD NOT BE POPULATED." at 6102,-318 h60
  text ".VariantName" at 5058,-434 h60
  text "ASSEMBLY VARIANT:" at 6097,-434 h60
  text ".VersionControl_RevNumber" at 1035.5,-656.17 h60
  text "SVN REV:" at 1541.5,-656.17 h60
  text ".PCB_Rev" at 2088,-656.17 h60
  text "REV:" at 2379.5,-656.17 h60
  text ".PRJ_Number" at 3224,-656.17 h60
  text "BOARD #:" at 3769.5,-656.17 h60
  text "PCB VIEWED FROM BOTTOM SIDE" at 6246,-656.17 h60
  text ".TID" at 3224,-859.5 h60
  text "TID #:" at 3769.5,-859.5 h60
  text "TEXAS INSTRUMENTS" at 904.5,-1064.84 h60
  text ".Print_Time" at 2169,-1064.84 h60
  text ".Print_Date" at 2898,-1064.84 h60
  text "GENERATED    :" at 3767.5,-1064.84 h60
  text ".plot_File_Name" at 5440.5,-1064.84 h60
  text "PLOT NAME =" at 6246,-1064.84 h60
M9 Title Sheet:
  drawing of 57 lines, arcs and shapes, not listed
  text "1" at 739.84,8036.5 h70
  text "2" at 3235.5,8036.5 h70
  text "3" at 5724.84,8036.5 h70
  text "4" at 8231.51,8036.5 h70
  text "5" at 10730.5,8036.5 h70
  text "6" at 13235.5,8036.5 h70
  text "A" at -416.5,6893.5 h70
  text "A" at 14383.5,6893.5 h70
  text "B" at -416.5,4513.5 h70
  text "B" at 14383.5,4513.5 h70
  text "C" at -416.5,2138.5 h70
  text "C" at 14383.5,2138.5 h70
  text "PROJECT TITLE:" at 11343.5,277.5 h45
  text ".PRJ_Title" at 11393.5,144.17 h70
  text "DESIGNED FOR:" at 11343.5,-23.5 h45
  text ".PRJ_Customer" at 11393.5,-163.5 h70
  text "D" at -416.5,-231.5 h70
  text "D" at 14383.5,-231.5 h70
  text "FILE NAME:" at 11343.5,-323.5 h45
  text ".PCB_File_Name_No_Path" at 11393.5,-443.5 h70
  text "Texas Instruments (TI) and/or its licensors do not warrant the accuracy or completeness of this specification" at 6374,-605.34 h45
  text "ENGINEER:" at 11343.5,-613.5 h45
  text "LAYOUT BY:" at 12848.5,-613.5 h45
  text "or any information contained therein. TI and/or its licensors do not warrant that this design will meet" at 6329.01,-718 h45
  text ".PRJ_Engineer" at 11393.5,-768.49 h70
  text ".PCB_Layout" at 12899,-768.49 h70
  text "the specifications, will be suitable for your application or fit for any particular purpose, or will operate in" at 6329.01,-830.67 h45
  text ".Layer_Name" at 577,-858.49 h60
  text "ALTIUM DESIGNER VERSION:" at 12848.5,-923.5 h45
  text "an implementation. TI and/or its licensors do not warrant that the design is production worthy. You should" at 6329.01,-943.33 h45
  text "completely validate and test your design implementation to confirm the system functionality for your application." at 6374,-1056 h45
  text ".print_Scale" at 11393.5,-1056.83 h70
  text ".Application_BuildNumber" at 12899,-1056.83 h70
  text "1" at 739.84,-1263.5 h70
  text "2" at 3235.5,-1263.5 h70
  text "3" at 5724.84,-1263.5 h70
  text "4" at 8231.51,-1263.5 h70
  text "5" at 10730.5,-1263.5 h70
  text "6" at 13235.5,-1263.5 h70
M10 Fab Notes:
  drawing of 173 lines, arcs and shapes, not listed
  text "DESIGN INFORMATION" at 12377.02,6201 h60
  text "MIN. TRACK WIDTH:" at 11732.46,6021 h60
  text "8" at 12828.7,6021 h60
  text "MIL" at 12983.46,6021 h60
  text "MIN. CLEARANCE:" at 11732.46,5889 h60
  text "0.2" at 12768.7,5889 h60
  text "mm" at 12983.46,5889 h60
  text "MIN. VIA PAD SIZE:" at 11732.46,5757 h60
  text "20" at 12798.71,5757 h60
  text "MIL" at 12983.46,5757 h60
  text "0.05mm (2MIL)" at 12427.46,5615.29 h60
  text "MINIMUM ANNULAR RING" at 11403.23,5611 h60
  text "EXTERNAL" at 13135.46,5611 h60
  text "PER" at 11603.23,5493 h60
  text "IPC-D-275 CLASS 2 LEVEL C" at 11823.23,5493 h60
  text "MIL, HOLES" at 13311.46,5380.71 h60
  text "+/-" at 12919,5380 h60
  text "+/-" at 13773,5380 h60
  text "REGISTRATION TOLERANCES:" at 11403.23,5375 h60
  text "METAL" at 12603,5375 h60
  text "5" at 13179.2,5375 h60
  text "3" at 14012.2,5375 h60
  text "MIL" at 14128.46,5375 h60
  text "+/-" at 13773,5262 h60
  text "HOLE SIZE TOLERANCE (UNLESS OTHERWISE SPECIFIED):" at 11403.23,5257 h60
  text "3" at 14012.2,5257 h60
  text "MIL" at 14128.46,5257 h60
  text "MATERIAL:" at 11328.46,5047.54 h60
  text "FR-4 High Tg" at 12314.9,4907.21 h60
  text "FR-408" at 11749.46,4898.64 h60
  text "OTHER" at 13237.46,4898.64 h60
  text "X" at 12160,4895 h60
  text "62 MIL (1.6mm) +/-10%" at 12069.56,4735.92 h60
  text "THICKNESS:" at 11403.23,4731.64 h60
  text "X" at 11941.4,4731.64 h60
  text "OTHER" at 13354.46,4731.64 h60
  text "TOLERANCE:" at 11403.23,4573.64 h60
  text "X" at 12242.53,4573.64 h60
  text "ANSI IPC-6012 TYPE 3 CLASS 2" at 12429.48,4573.64 h60
  text "OTHER +/-" at 12429.46,4417.64 h60
  text "BOW & TWIST:" at 11403.23,4260.64 h60
  text "X" at 12242.53,4260.64 h60
  text "ANSI IPC-6012 TYPE 3 CLASS 2" at 12429.48,4260.64 h60
  text "OTHER +/-" at 12429.46,4102.13 h60
  text "DRILLING:" at 11328.46,3963.64 h60
  text "REFERENCE:" at 11403.23,3846.64 h60
  text "X" at 12051.46,3846.64 h60
  text "AS SHOWN" at 12238.46,3846.64 h60
  text "X" at 12952.46,3846.64 h60
  text "NC_DRILL FILES" at 13089.46,3846.64 h60
  text "PTH COPPER THICKNESS:" at 11403.23,3688.64 h60
  text "X" at 12533.46,3688.64 h60
  text "20-30 um" at 12670.46,3688.64 h60
  text "OTHER" at 13387.46,3688.64 h60
  text "BOARD FINISH:" at 11328.46,3529.64 h60
  text "SILKSCREEN:" at 11483.68,3411.64 h60
  text "X" at 12432.46,3411.64 h60
  text "TOP" at 12558.46,3411.64 h60
  text "X" at 12942.46,3411.64 h60
  text "BOTTOM" at 13069.46,3411.64 h60
  text "SILKSCREEN COLOR:" at 11483.68,3244.64 h60
  text "X" at 12431.42,3244.64 h60
  text "WHITE" at 12558.46,3244.64 h60
  text "OTHER" at 13069.46,3244.64 h60
  text "X" at 12562.42,3085.44 h60
  text "GREEN" at 12689.46,3085.44 h60
  text "OTHER" at 13307.46,3085.44 h60
  text "SOLDER RESIST COLOR:" at 11483.68,3074.64 h60
  text "X" at 12562.42,2915.44 h60
  text "MATTE" at 12689.46,2915.44 h60
  text "SEMI-GLOSS" at 13307,2914.8 h60
  text "IMMERSION GOLD (ENIG)" at 12389.46,2726.92 h60
  text "ENEPIG" at 13727,2723.64 h60
  text "SURFACE FINISH:" at 11328.46,2722.64 h60
  text "X" at 12202.51,2722.64 h60
  text "IMM. TIN/SILVER OR EQUIV" at 11658,2565.64 h60
  text "OTHER" at 13089.46,2565.64 h60
  text "ARRAY/PANEL:" at 11328.46,2386.64 h60
  text "CUT AND TRIM PER M1 BOARD OUTLINE" at 12389.46,2382.35 h60
  text "N.C. ROUTE" at 12389.46,2230.64 h60
  text "X" at 13068.46,2230.64 h60
  text "V. SCORE" at 13255.46,2230.64 h60
  text "CERTIFICATION:" at 11328.46,2093.64 h60
  text "MATERIALS AND WORKMANSHIP FOR ALL PCBS" at 12053.46,2093.64 h60
  text "TO MEET OR EXCEED THE REQUIREMENTS OF:" at 12053.46,1995.64 h60
  text "X" at 11679.96,1859.13 h60
  text "ANSI IPC-A-600F CLASS ->" at 11818.96,1859.13 h60
  text "X" at 13458.02,1859.13 h60
  text "2" at 13576.96,1859.14 h60
  text "1" at 13261.96,1857.64 h60
  text "3" at 13930.96,1857.64 h60
  text "X" at 12494.02,1699.64 h60
  text "RoHS" at 12630.96,1699.64 h60
  text "OTHER" at 13275.36,1699.64 h60
  text "PER ORDER" at 13672.42,1699.64 h60
  text "ALL BOARDS MUST MEET OR EXCEED UL94-V0 REQUIREMENTS." at 11356,1534 h60
  text "PCB MUST BEAR THE UL94V-0 UL REGISTERED MATERIAL ID NUMBER" at 11356,1414 h60
  text "ADDITIONAL REQUIREMENTS:" at 11328.46,1240.64 h60
  text "MICROSECTION:" at 11403.23,1125.64 h60
  text "YES" at 12308.96,1125.64 h60
  text "REQUIRED" at 13170.46,969.49 h60
  text "BARE BOARD ELEC. TEST:" at 11403.23,966.64 h60
  text "NONE" at 12708.96,966.64 h60
  text "X" at 13043.46,966.64 h60
  text "PER ORDER" at 13762.46,966.64 h60
  text ".Layer_Name" at 577,-858.49 h60
M11 Gerber Information:
  lines w10: -292,-930.17 6308,-930.17 ; -292,-726.83 6310,-726.83 ; -292,-523.5 -292,-1133.5 3713,-1133.5 6310,-1133.5 6310,-523.5 -291.5,-523.5 -291.5,-1133.5 1284,-1133.5 ; 2173,-1133.5 2173,-523.5 ; 3440,-726.83 3440,-523.5 ; 4280,-726.83 4280,-523.5 ; 4902,-1140 4902,-937.17
  text "ALL ARTWORK VIEWED FROM TOP SIDE" at -228.5,-655.67 h60
  text "BOARD #:" at 2248,-655.67 h60
  text ".PRJ_Number" at 2793.5,-655.67 h60
  text "REV:" at 3638,-655.67 h60
  text ".PCB_Rev" at 3929.5,-655.67 h60
  text "SVN REV:" at 4476,-655.67 h60
  text ".VersionControl_RevNumber" at 4982,-655.67 h60
  text "LAYER NAME =" at -228.5,-858.49 h60
  text "TID #:" at 2248,-859 h60
  text ".TID" at 2793.5,-859 h60
  text "PLOT NAME =" at -228.5,-1064.34 h60
  text ".plot_File_Name" at 577,-1064.34 h60
  text "GENERATED    :" at 2250,-1064.34 h60
  text ".Print_Date" at 3119.5,-1064.34 h60
  text ".Print_Time" at 3848.5,-1064.34 h60
  text "TEXAS INSTRUMENTS" at 5113,-1064.34 h60
M12 Stackup:
  drawing of 191 lines, arcs and shapes, not listed
  text "Layer" at 9790.58,7830 h60
  text "Name" at 10200.49,7830 h60
  text "Material" at 11130.23,7830 h60
  text "Thickness" at 11990,7830 h60
  text "Constant" at 12639.84,7830 h60
  text "Board Layer Stack" at 13209.7,7830 h60
  text "1" at 9790.58,7710 h60
  text "Top Overlay" at 10200.49,7710 h60
  text "2" at 9790.58,7590 h60
  text "Top Solder" at 10200.49,7590 h60
  text "Solder Resist" at 11130.23,7590 h60
  text "0.40mil" at 11990,7590 h60
  text "3.5" at 12639.84,7590 h60
  text "3" at 9790.58,7470 h60
  text "Top Layer" at 10200.49,7470 h60
  text "Copper" at 11130.23,7470 h60
  text "1.40mil" at 11990,7470 h60
  text "4" at 9790.58,7350 h60
  text "Dielectric1" at 10200.49,7350 h60
  text "FR-4" at 11130.23,7350 h60
  text "59.20mil" at 11990,7350 h60
  text "4.8" at 12639.84,7350 h60
  text "5" at 9790.58,7230 h60
  text "Bottom Layer" at 10200.49,7230 h60
  text "Copper" at 11130.23,7230 h60
  text "1.40mil" at 11990,7230 h60
  text "6" at 9790.58,7110 h60
  text "Bottom Solder" at 10200.49,7110 h60
  text "Solder Resist" at 11130.23,7110 h60
  text "0.40mil" at 11990,7110 h60
  text "3.5" at 12639.84,7110 h60
  text "7" at 9790.58,6990 h60
  text "Bottom Overlay" at 10200.49,6990 h60
  text ".Layer_Name" at 577,-858.49 h60
M13 Component Bodies Top:
  text ".Layer_Name" at 577,-858.49 h60
M14 Component Bodies Bottom:
  text ".Layer_Name" at 577,-858.49 h60
M15 Courtyards Top:
  text ".Layer_Name" at 577,-858.49 h60
M16 Courtyards Bottom:
  text ".Layer_Name" at 577,-858.49 h60
Drill Drawing:
  circle w10: c5563.8,3141.62 r27.66
  lines w10: 5536.14,2505.5 5549.97,2505.5 5563.8,2491.67 5577.63,2505.5 5591.46,2505.5 5577.63,2519.33 5591.46,2533.15 5577.63,2533.15 5563.8,2546.98 5549.97,2533.15 5536.14,2533.15 5549.97,2519.33 5536.14,2505.5 ; 5536.14,2616.13 5591.46,2616.13 5591.46,2671.44 5536.14,2671.44 5536.14,2616.13 ; 5536.14,2795.9 5591.46,2795.9 5563.8,2740.59 5536.14,2795.9 ; 5536.14,2865.04 5591.46,2865.04 5591.46,2920.36 5536.14,2920.36 5536.14,2865.04 ; 5536.14,2989.5 5563.8,3003.33 5591.46,2989.5 5577.63,3017.16 5591.46,3044.82 5563.8,3030.99 5536.14,3044.82 5549.97,3017.16 5536.14,2989.5 ; 5536.14,3293.74 5591.46,3293.74 5563.8,3238.42 5536.14,3293.74 ; 5547.21,2876.11 5580.39,2876.11 5580.39,2909.3 5547.21,2909.3 5547.21,2876.11 ; 5547.21,3282.67 5580.39,3282.67 5563.8,3249.48 5547.21,3282.67
  lines w12: 5486,2454.33 7465.4,2454.33 ; 5486,3325.54 7465.4,3325.54 ; 5824.17,2329.87 5824.17,3450 ; 6156.28,2329.87 6156.28,3450 ; 6793.29,2329.87 6793.29,3450 ; 7052.64,2329.87 7052.64,3450 ; 5486,2329.87 7465.4,2329.87 7465.4,3450 5486,3450 5486,2329.87
  text "Symbol" at 5560.68,3362.88 h72
  text "Quantity" at 5861.51,3362.88 h72
  text "Finished Hole Size" at 6193.62,3362.88 h72
  text "Plated" at 6830.62,3362.88 h72
  text "Hole Type" at 7089.98,3362.88 h72
  text "10" at 5861.51,3238.42 h60
  text "10.00mil (0.254mm)" at 6193.62,3238.42 h60
  text "PTH" at 6830.62,3238.42 h60
  text "Round" at 7089.98,3238.42 h60
  text "12" at 5861.51,3113.96 h60
  text "25.00mil (0.635mm)" at 6193.62,3113.96 h60
  text "PTH" at 6830.62,3113.96 h60
  text "Round" at 7089.98,3113.96 h60
  text "13" at 5861.51,2989.5 h60
  text "33.46mil (0.850mm)" at 6193.62,2989.5 h60
  text "PTH" at 6830.62,2989.5 h60
  text "Round" at 7089.98,2989.5 h60
  text "1" at 5861.51,2865.04 h60
  text "33.54mil (0.852mm)" at 6193.62,2865.04 h60
  text "PTH" at 6830.62,2865.04 h60
  text "Round" at 7089.98,2865.04 h60
  text "7" at 5861.51,2740.59 h60
  text "40.00mil (1.016mm)" at 6193.62,2740.59 h60
  text "PTH" at 6830.62,2740.59 h60
  text "Round" at 7089.98,2740.59 h60
  text "9" at 5861.51,2616.13 h60
  text "50.00mil (1.270mm)" at 6193.62,2616.13 h60
  text "PTH" at 6830.62,2616.13 h60
  text "Round" at 7089.98,2616.13 h60
  text "4" at 5861.51,2491.67 h60
  text "98.43mil (2.500mm)" at 6193.62,2491.67 h60
  text "PTH" at 6830.62,2491.67 h60
  text "Round" at 7089.98,2491.67 h60
  text "56 Total" at 5861.51,2367.21 h60
  text ".Layer_Name" at 577,-858.49 h60

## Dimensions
0,-400 to 1000,-400 on M2 Board Dimensions
0,0 to 0,1900 on M2 Board Dimensions
0,0 to 3500,0 on M2 Board Dimensions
